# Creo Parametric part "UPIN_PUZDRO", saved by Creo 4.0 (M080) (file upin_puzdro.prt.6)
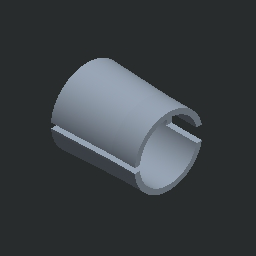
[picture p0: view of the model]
Units: millimeter Kilogram Sec (mmKs); MM, KILOGRAM, SECS
Materials in the file: OCEL_N

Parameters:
  MFG_WP_MATERIAL = "OCEL"
  NAZOV = "UPIN_PUZDRO"
  PTC_MATERIAL_NAME = "OCEL_N"

Other parameters: HMOTNOST, HUSTOTA, D22, D4, D28, D1, D0, D26

Created from: UPIN_PUZDRA.PRT

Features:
  1. datum plane "DTM3"
  2. cut
  3. cut

Other named items: BLIND

Layers: 1, 2, 3, 4, 5, 6, 7, 8, 9, 10, 11, 12, 13, 14, 15, 16, 17, 18, 19, 20, 21, 22, 23, 24, 25, 26, 27, 28, 29, 30, 31, 32

Family table entries: GENERIC, UPIN_PUZDRO_H204, UPIN_PUZDRO, value(d_val), 2/4, 2/8, value(i_val), UPIN_PUZDRO_H304, UPIN_PUZDRO, !/1, 2/4, 2/<, UPIN_PUZDRO_H205, UPIN_PUZDRO, !/4, 2/9, 2/:, 2/ , UPIN_PUZDRO_H305, UPIN_PUZDRO, !/4, 2/9, 2/=, 2/ , UPIN_PUZDRO_H2305, UPIN_PUZDRO, !/4, 2/9, 2/ , UPIN_PUZDRO_H206, UPIN_PUZDRO, !/9, 2/>, 2/;, 2/ , UPIN_PUZDRO_H306, UPIN_PUZDRO, !/9, 2/>, 2/?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

Surfaces: 10 plane, 4 cylinder, 1 cone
